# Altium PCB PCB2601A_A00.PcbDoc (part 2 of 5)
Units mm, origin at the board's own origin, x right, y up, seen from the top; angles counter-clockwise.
Board outline 30.4 x 51 mm, 8 copper layers (Top Layer, Signal Layer 2, Signal Layer 3, Signal Layer 4, Signal Layer 5, Signal Layer 6, Signal Layer 7, Bottom Layer), stack 1.492 mm thick; 194 components, 130 nets, 5039 pads, 478 vias.
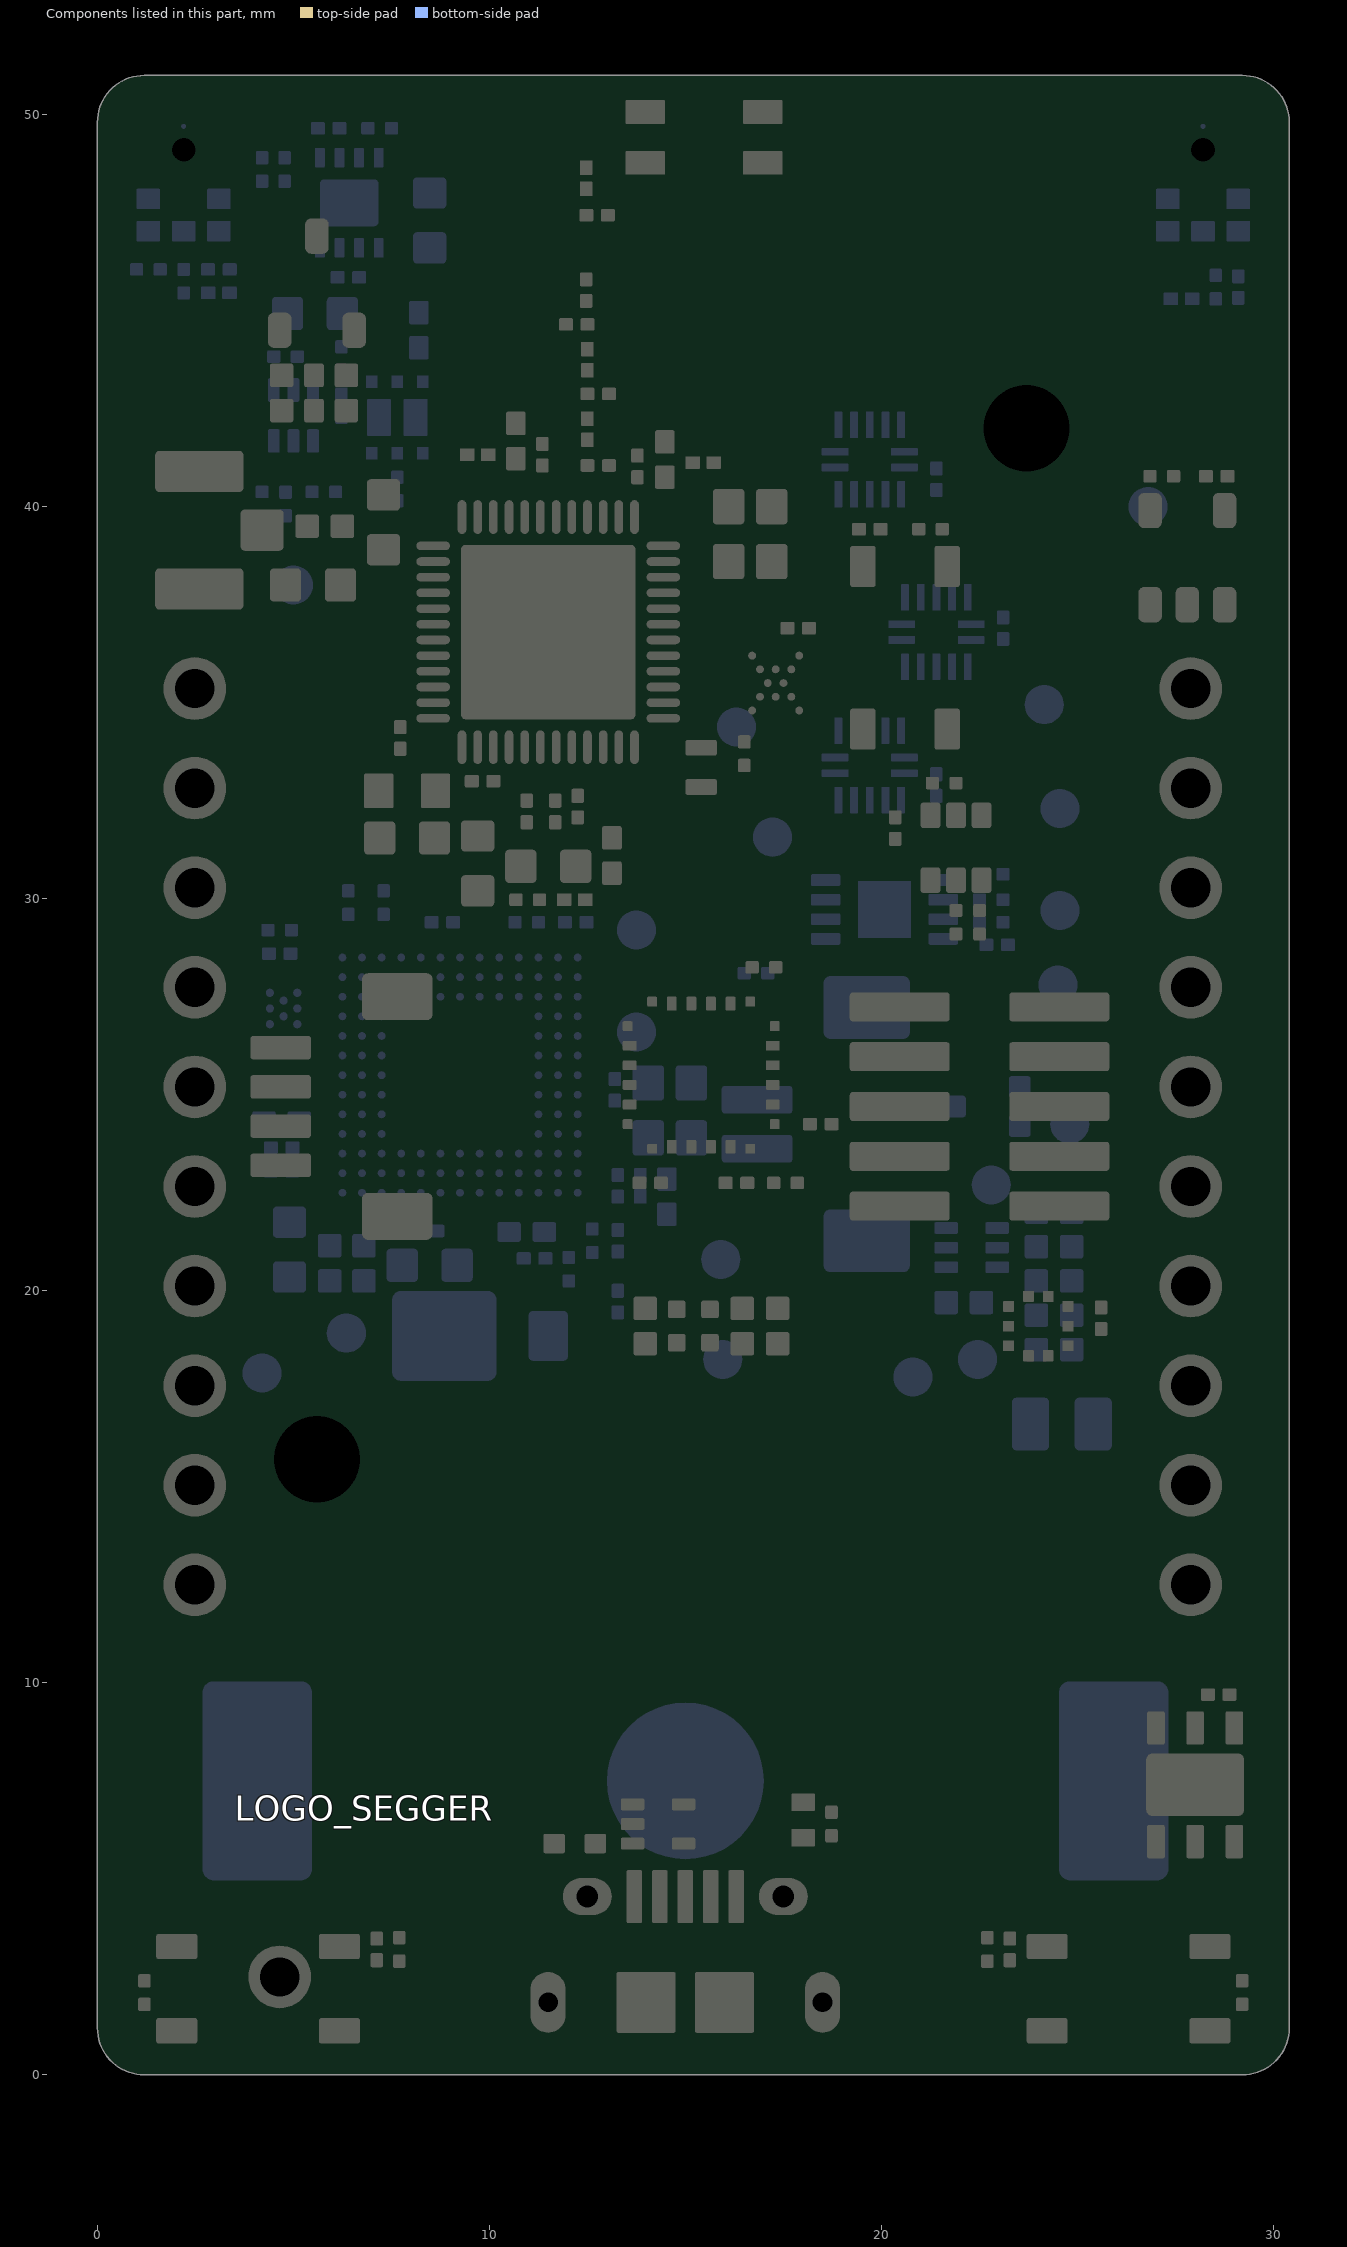
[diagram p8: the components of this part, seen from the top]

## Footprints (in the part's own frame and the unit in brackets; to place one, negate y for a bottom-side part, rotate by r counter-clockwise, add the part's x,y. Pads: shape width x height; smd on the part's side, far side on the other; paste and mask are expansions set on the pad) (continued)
LOGO_SEGGER_8.0X4.0_SM [mil] "(210607)" (continued)
  round 0.8 on Mech2: 1(-157.24,-66.18) 1(-157.24,-66.18) 1(-157.24,-65.7) 1(-157.24,-64.1) 1(-157.24,-62.5) 1(-157.24,-60.9) 1(-157.24,-59.22) 1(-157.24,-57.62) 1(-157.24,-56.02) 1(-157.24,-54.42) 1(-157.24,-52.82) 1(-157.24,-51.22) 1(-157.24,-49.62) 1(-157.24,-48.02) 1(-157.24,-46.42) 1(-157.24,-44.82) 1(-157.24,-43.14) 1(-157.24,-41.54) 1(-157.24,-39.94) 1(-157.24,-38.34) 1(-157.24,-36.74) 1(-157.24,-35.14) 1(-157.24,-33.54) 1(-157.24,-31.94) 1(-157.24,-30.34) 1(-157.24,-28.74) 1(-157.24,-27.06) 1(-157.24,-25.46) 1(-157.24,-23.86) 1(-157.24,-22.26) 1(-157.24,-20.66) 1(-157.24,-19.06) 1(-157.24,-17.46) 1(-157.24,-15.86) 1(-157.24,-14.26) 1(-157.24,-12.66) 1(-157.24,-10.98) 1(-157.24,-9.38) 1(-157.24,-7.78) 1(-157.24,-6.18) 1(-157.24,-4.58) 1(-157.24,-2.98) 1(-157.24,-1.38) 1(-157.24,0.22) 1(-157.24,1.82) 1(-157.24,3.42) 1(-157.24,5.1) 1(-157.24,6.7) 1(-157.24,8.3) 1(-157.24,9.9) 1(-157.24,11.5) 1(-157.24,13.1) 1(-157.24,14.7) 1(-157.24,16.3) 1(-157.24,17.9) 1(-157.24,19.5) 1(-157.24,21.18) 1(-157.24,22.78) 1(-157.24,24.38) 1(-157.24,25.98) 1(-157.24,27.58) 1(-157.24,29.18) 1(-157.24,30.78) 1(-157.24,32.38) 1(-157.24,33.98) 1(-157.24,35.58) 1(-157.24,37.26) 1(-157.24,38.86) 1(-157.24,40.46) 1(-157.24,42.06) 1(-157.24,43.66) 1(-157.24,45.26) 1(-157.24,46.86) 1(-157.24,48.46) 1(-157.24,50.06) 1(-157.24,51.66) 1(-157.24,53.34) 1(-157.24,54.94) 1(-157.24,56.54) 1(-157.24,58.14) 1(-157.24,59.74) 1(-157.24,61.34) 1(-157.24,62.94) 1(-157.24,64.54) 1(-157.24,66.14) 1(-157.24,66.38) 1(-157.24,66.38) 1(-157.08,-67.3) 1(-157.08,67.74) 1(-157,-68.1) 1(-157,-68.1) 1(-157,68.3) 1(-157,68.3) 1(-156.84,68.94) 1(-156.84,68.94) 1(-156.76,-68.9) 1(-156.68,-69.38) 1(-156.68,-69.38) 1(-156.68,69.42) 1(-156.68,69.5) 1(-156.68,69.5) 1(-156.52,-69.94) 1(-156.52,-69.94) 1(-156.52,70.14) 1(-156.52,70.14) 1(-156.28,-70.5) 1(-156.28,-70.5) 1(-156.2,-70.5) 1(-156.12,71.02) 1(-156.04,-71.14) 1(-156.04,-71.14) 1(-155.8,-71.7) 1(-155.8,-71.7) 1(-155.8,71.82) 1(-155.8,71.82) 1(-155.48,-72.26) 1(-155.48,-72.26) 1(-155.48,-72.1) 1(-155.32,72.62) 1(-155.16,72.94) 1(-155.16,72.94) 1(-154.84,-73.22) 1(-154.84,-73.22) 1(-154.84,73.42) 1(-154.84,73.42) 1(-154.44,-73.78) 1(-154.44,-73.78) 1(-154.44,-73.7) 1(-154.2,74.22) 1(-154.04,-74.18) 1(-154.04,-74.18) 1(-153.64,74.86) 1(-153.64,74.86) 1(-153.24,-75.14) 1(-153.24,-75.14) 1(-152.92,-75.3) 1(-152.76,75.74) 1(-152.76,75.74) 1(-152.68,75.82) 1(-152.28,76.06) 1(-152.28,76.06) 1(-151.8,-76.34) 1(-151.8,-76.34) 1(-151.32,-76.66) 1(-151.32,-76.66) 1(-151.32,76.86) 1(-151.32,76.86) 1(-150.76,-76.98) 1(-150.76,77.18) 1(-150.76,77.18) 1(-150.68,-66.18) 1(-150.68,-66.18) 1(-150.68,-65.7) 1(-150.68,-64.1) 1(-150.68,-62.5) 1(-150.68,-60.9) 1(-150.68,-59.22) 1(-150.68,-57.62) 1(-150.68,-56.02) 1(-150.68,-54.42) 1(-150.68,-52.82) 1(-150.68,-51.22) 1(-150.68,-49.62) 1(-150.68,-48.02) 1(-150.68,-46.42) 1(-150.68,-44.82) 1(-150.68,-43.14) 1(-150.68,-41.54) 1(-150.68,-39.94) 1(-150.68,-38.34) 1(-150.68,-36.74) 1(-150.68,-35.14) 1(-150.68,-33.54) 1(-150.68,-31.94) 1(-150.68,-30.34) 1(-150.68,-28.74) 1(-150.68,-27.06) 1(-150.68,-25.46) 1(-150.68,-23.86) 1(-150.68,-22.26) 1(-150.68,-20.66) 1(-150.68,-19.06) 1(-150.68,-17.46) 1(-150.68,-15.86) 1(-150.68,-14.26) 1(-150.68,-12.66) 1(-150.68,-10.98) 1(-150.68,-9.38) 1(-150.68,-7.78) 1(-150.68,-6.18) 1(-150.68,-4.58) 1(-150.68,-2.98) 1(-150.68,-1.38) 1(-150.68,0.22) 1(-150.68,1.82) 1(-150.68,3.42) 1(-150.68,5.1) 1(-150.68,6.7) 1(-150.68,8.3) 1(-150.68,9.9) 1(-150.68,11.5) 1(-150.68,13.1) 1(-150.68,14.7) 1(-150.68,16.3) 1(-150.68,17.9) 1(-150.68,19.5) 1(-150.68,21.18) 1(-150.68,22.78) 1(-150.68,24.38) 1(-150.68,25.98) 1(-150.68,27.58) 1(-150.68,29.18) 1(-150.68,30.78) 1(-150.68,32.38) 1(-150.68,33.98) 1(-150.68,35.58) 1(-150.68,37.26) 1(-150.68,38.86) 1(-150.68,40.46) 1(-150.68,42.06) 1(-150.68,43.66) 1(-150.68,45.26) 1(-150.68,46.86) 1(-150.68,48.46) 1(-150.68,50.06) 1(-150.68,51.66) 1(-150.68,53.34) 1(-150.68,54.94) 1(-150.68,56.54) 1(-150.68,58.14) 1(-150.68,59.74) 1(-150.68,61.34) 1(-150.68,62.94) 1(-150.68,64.54) 1(-150.68,66.14) 1(-150.68,66.38) 1(-150.68,66.38) 1(-150.6,-66.82) 1(-150.6,-66.82) 1(-150.6,-66.5) 1(-150.6,-66.5) 1(-150.6,66.7) 1(-150.6,66.7) 1(-150.6,67.02) 1(-150.6,67.02) 1(-150.44,-67.46) 1(-150.44,-67.46) 1(-150.44,-67.3) 1(-150.44,67.66) 1(-150.44,67.66) 1(-150.36,67.74) 1(-150.28,-67.78) 1(-150.28,-67.78) 1(-150.28,67.98) 1(-150.28,67.98) 1(-150.2,-77.3) 1(-150.2,-77.3) 1(-150.2,-68.1) 1(-150.2,-68.1) 1(-150.2,68.3) 1(-150.2,68.3) 1(-150.2,77.42) 1(-150.2,77.42) 1(-150.2,77.42) 1(-150.04,-68.42) 1(-150.04,-68.42) 1(-150.04,68.54) 1(-150.04,68.54) 1(-149.96,-68.66) 1(-149.96,-68.66) 1(-149.96,68.86) 1(-149.96,68.86) 1(-149.8,-68.98) 1(-149.8,-68.98) 1(-149.8,-68.9) 1(-149.8,69.1) 1(-149.8,69.1) 1(-149.72,-77.54) 1(-149.72,-77.54) 1(-149.72,77.74) 1(-149.72,77.74) 1(-149.64,69.42) 1(-149.64,69.42) 1(-149.64,69.42) 1(-149.48,-69.46) 1(-149.48,-69.46) 1(-149.48,69.66) 1(-149.48,69.66) 1(-149.24,-69.7) 1(-149.24,-69.7) 1(-149.24,69.9) 1(-149.24,69.9) 1(-149.08,-77.78) 1(-149.08,-77.78) 1(-149.08,-69.94) 1(-149.08,-69.94) 1(-149.08,70.14) 1(-149.08,70.14) 1(-149.08,77.98) 1(-149.08,77.98) 1(-148.84,-70.18) 1(-148.84,-70.18) 1(-148.68,-70.42) 1(-148.68,-70.42) 1(-148.52,-78.02) 1(-148.52,-78.02) 1(-148.52,78.14) 1(-148.52,78.14) 1(-148.44,-70.58) 1(-148.44,-70.58) 1(-148.44,-70.5) 1(-148.44,70.78) 1(-148.44,70.78) 1(-148.2,70.94) 1(-148.2,70.94) 1(-148.12,71.02) 1(-148.04,-70.98) 1(-148.04,-70.98) 1(-148.04,71.18) 1(-148.04,71.18) 1(-147.88,-78.18) 1(-147.88,-78.18) 1(-147.88,78.3) 1(-147.88,78.3) 1(-147.8,-71.14) 1(-147.8,-71.14) 1(-147.8,71.34) 1(-147.8,71.34) 1(-147.48,-71.3) 1(-147.48,-71.3) 1(-147.48,71.42) 1(-147.48,71.42) 1(-147.32,-78.34) 1(-147.32,-78.34) 1(-147.32,78.46) 1(-147.32,78.46) 1(-147.24,-71.38) 1(-147.24,-71.38) 1(-147,-71.54) 1(-147,-71.54) 1(-147,71.74) 1(-147,71.74) 1(-146.76,-71.62) 1(-146.76,-71.62) 1(-146.76,71.82) 1(-146.76,71.82) 1(-146.68,78.62) 1(-146.68,78.62) 1(-146.44,-71.78) 1(-146.44,-71.78) 1(-146.44,71.9) 1(-146.44,71.9) 1(-146.04,78.7) 1(-146.04,78.7) 1(-145.96,-71.94) 1(-145.96,-71.94) 1(-145.96,72.06) 1(-145.96,72.06) 1(-145.64,-71.94) 1(-145.64,-71.94) 1(-145.64,72.14) 1(-145.64,72.14) 1(-145.4,-78.58) 1(-145.4,-78.58) 1(-145.4,-72.02) 1(-145.4,-72.02) 1(-145.4,72.14) 1(-145.4,72.14) 1(-145.4,78.7) 1(-145.4,78.7) 1(-145.08,72.22) 1(-145.08,72.22) 1(-144.76,78.78) 1(-144.76,78.78) 1(-141.32,-53.06) 1(-141.32,-53.06) 1(-141.32,-52.58) 1(-141.32,-52.1) 1(-141.32,-52.1) 1(-141.32,52.3) 1(-141.32,52.3) 1(-141.32,53.26) 1(-141.32,53.26) 1(-141.24,-53.46) 1(-141.24,-53.46) 1(-141.24,-53.3) 1(-141.24,-53.3) 1(-141.24,-51.94) 1(-141.24,-51.94) 1(-141.24,52.06) 1(-141.24,52.06) 1(-141.24,53.5) 1(-141.24,53.5) 1(-141.24,53.5) 1(-141.24,53.66) 1(-141.24,53.66) 1(-141.16,-53.7) 1(-141.16,-53.7) 1(-141.16,-51.7) 1(-141.16,-51.7) 1(-141.16,51.9) 1(-141.16,51.9) 1(-141.16,51.9) 1(-141.16,53.9) 1(-141.16,53.9) 1(-141.08,-51.38) 1(-141.08,-51.38) 1(-141.08,51.5) 1(-141.08,51.5) 1(-141,-53.94) 1(-141,-53.94) 1(-141,54.06) 1(-141,54.06) 1(-140.92,-54.1) 1(-140.92,-54.1) 1(-140.92,54.3) 1(-140.92,54.3) 1(-140.84,-51.06) 1(-140.84,-51.06) 1(-140.84,-26.18) 1(-140.84,-26.18) 1(-140.84,-24.58) 1(-140.84,-22.9) 1(-140.84,-21.3) 1(-140.84,-19.7) 1(-140.84,-18.1) 1(-140.84,-16.5) 1(-140.84,-14.9) 1(-140.84,-13.3) 1(-140.84,-11.7) 1(-140.84,-10.1) 1(-140.84,-8.5) 1(-140.84,-6.82) 1(-140.84,-5.22) 1(-140.84,-3.62) 1(-140.84,-2.02) 1(-140.84,-0.42) 1(-140.84,1.18) 1(-140.84,2.78) 1(-140.84,4.38) 1(-140.84,5.98) 1(-140.84,7.58) 1(-140.84,9.26) 1(-140.84,10.86) 1(-140.84,12.46) 1(-140.84,14.06) 1(-140.84,15.66) 1(-140.84,17.26) 1(-140.84,18.86) 1(-140.84,20.46) 1(-140.84,22.06) 1(-140.84,23.66) 1(-140.84,25.34) 1(-140.84,26.3) 1(-140.84,26.3) 1(-140.84,51.18) 1(-140.84,51.18) 1(-140.76,-54.18) 1(-140.76,-50.98) 1(-140.68,-50.66) 1(-140.68,-50.66) 1(-140.68,50.86) 1(-140.68,50.86) 1(-140.6,-54.58) 1(-140.6,-54.58) 1(-140.6,54.78) 1(-140.6,54.78) 1(-140.44,-50.34) 1(-140.44,-50.34) 1(-140.44,50.46) 1(-140.44,50.46) 1(-140.36,54.94) 1(-140.36,54.94) 1(-140.28,50.3) 1(-140.2,-49.94) 1(-140.2,-49.94) 1(-140.2,50.14) 1(-140.2,50.14) 1(-140.2,55.1) 1(-140.04,25.34) 1(-139.88,-49.62) 1(-139.88,-49.62) 1(-139.88,49.82) 1(-139.88,49.82) 1(-139.88,55.42) 1(-139.88,55.42) 1(-139.72,-49.38) 1(-139.64,-55.54) 1(-139.64,-55.54) 1(-139.64,-24.58) 1(-139.64,55.74) 1(-139.64,55.74) 1(-139.16,-55.86) 1(-139,48.7) 1(-138.84,23.66) 1(-138.52,-47.78) 1(-138.36,-56.5) 1(-138.36,-56.5) 1(-138.36,-22.9) 1(-138.36,56.7) 1(-138.36,56.7) 1(-138.28,56.7) 1(-138.04,-56.66) 1(-138.04,-56.66) 1(-137.8,47.1) 1(-137.72,-56.9) 1(-137.72,-56.9) 1(-137.72,57.02) 1(-137.72,57.02) 1(-137.64,22.06) 1(-137.48,-56.98) 1(-137.48,-56.98) 1(-137.48,57.18) 1(-137.48,57.18) 1(-137.32,-46.18) 1(-137.16,-57.14) 1(-137.16,-57.14) 1(-137.16,-21.3) 1(-137.16,57.26) 1(-137.16,57.26) 1(-136.92,57.42) 1(-136.92,57.42) 1(-136.6,45.5) 1(-136.44,-57.38) 1(-136.44,-57.38) 1(-136.44,20.46) 1(-136.44,57.58) 1(-136.44,57.58) 1(-136.2,-57.38) 1(-136.2,-57.38) 1(-136.12,-44.58) 1(-135.96,-57.46) 1(-135.96,-57.46) 1(-135.96,-19.7) 1(-135.72,-57.46) 1(-135.72,-57.46) 1(-135.56,-57.38) 1(-135.56,-57.38) 1(-135.4,43.9) 1(-135.32,57.58) 1(-135.32,57.58) 1(-135.24,18.86) 1(-135.16,-57.38) 1(-135.16,-57.38) 1(-135,-57.3) 1(-135,-57.3) 1(-135,57.42) 1(-135,57.42) 1(-134.92,-42.98) 1(-134.76,-57.22) 1(-134.76,-57.22) 1(-134.76,-18.1) 1(-134.76,57.42) 1(-134.76,57.42) 1(-134.44,57.26) 1(-134.44,57.26) 1(-134.28,-56.98) 1(-134.28,-56.98) 1(-134.28,57.1) 1(-134.28,57.1) 1(-134.2,42.3) 1(-134.04,17.26) 1(-133.96,-56.66) 1(-133.96,-56.66) 1(-133.72,-41.38) 1(-133.72,56.7) 1(-133.64,-56.42) 1(-133.64,-56.42) 1(-133.64,56.62) 1(-133.64,56.62) 1(-133.56,-16.5) 1(-133.16,-55.86) 1(-133.16,-55.78) 1(-133.16,-55.78) 1(-133.16,55.98) 1(-133.16,55.98) 1(-133,40.62) 1(-132.84,-55.46) 1(-132.84,-55.46) 1(-132.84,15.66) 1(-132.84,55.58) 1(-132.84,55.58) 1(-132.6,-55.14) 1(-132.6,-55.14) 1(-132.6,55.26) 1(-132.6,55.26) 1(-132.52,-39.78) 1(-132.44,55.1) 1(-132.36,-14.9) 1(-131.88,-54.18) 1(-131.8,39.02) 1(-131.64,14.06) 1(-131.24,-38.1) 1(-131.24,53.5) 1(-131.16,-13.3) 1(-130.68,-52.58) 1(-130.6,37.42) 1(-130.36,12.46) 1(-130.04,-36.5) 1(-130.04,51.9) 1(-129.96,-11.7) 1(-129.48,-50.98) 1(-129.4,35.82) 1(-129.16,10.86) 1(-128.84,-34.9) 1(-128.84,50.3) 1(-128.76,-10.1) 1(-128.28,-49.38) 1(-128.12,34.22) 1(-127.96,9.26) 1(-127.64,-33.3) 1(-127.64,48.7) 1(-127.56,-8.5) 1(-127.08,-47.78) 1(-126.92,32.62) 1(-126.76,7.58) 1(-126.44,-31.7) 1(-126.44,47.1) 1(-126.36,-6.82) 1(-125.88,-46.18) 1(-125.72,31.02) 1(-125.56,5.98) 1(-125.24,-30.1) 1(-125.24,45.5) 1(-125.16,-5.22) 1(-124.68,-44.58) 1(-124.52,29.42) 1(-124.36,4.38) 1(-124.04,-28.5) 1(-123.96,-3.62) 1(-123.96,43.9) 1(-123.48,-42.98) 1(-123.32,27.82) 1(-123.16,2.78) 1(-122.84,-26.9) 1(-122.76,-2.02) 1(-122.76,42.3) 1(-122.28,-41.38) 1(-122.12,26.22) 1(-121.96,1.18) 1(-121.64,-25.3) 1(-121.56,40.62) 1(-121.48,-0.42) 1(-121.16,0.06) 1(-121.16,0.06) 1(-121.08,-39.78) 1(-120.92,24.54) 1(-120.44,-23.7) 1(-120.36,39.02) 1(-119.8,-38.1) 1(-119.72,22.94) 1(-119.24,-22.02) 1(-119.16,37.42) 1(-118.6,-36.5) 1(-118.52,21.34) 1(-118.04,-20.42) 1(-117.96,35.82) 1(-117.4,-34.9) 1(-117.32,19.74) 1(-116.84,-18.82) 1(-116.76,34.22) 1(-116.2,-33.3) 1(-116.12,18.14) 1(-115.64,-17.22) 1(-115.56,32.62) 1(-115,-31.7) 1(-114.92,16.54) 1(-114.44,-15.62) 1(-114.36,31.02) 1(-113.8,-30.1) 1(-113.72,14.94) 1(-113.24,-14.02) 1(-113.16,-53.06) 1(-113.16,-53.06) 1(-113.16,-52.58) 1(-113.16,-52.26) 1(-113.16,-52.26) 1(-113.16,29.42) 1(-113.16,52.38) 1(-113.16,52.38) 1(-113.16,53.18) 1(-113.16,53.18) 1(-113.08,-53.22) 1(-113.08,-53.22) 1(-113.08,-52.02) 1(-113.08,-52.02) 1(-113.08,-51.86) 1(-113.08,-51.86) 1(-113.08,52.06) 1(-113.08,52.06) 1(-113.08,52.22) 1(-113.08,52.22) 1(-113.08,53.42) 1(-113.08,53.42) 1(-113,-53.46) 1(-113,-53.46) 1(-113,-51.62) 1(-113,-51.62) 1(-113,51.82) 1(-113,51.82) 1(-113,51.98) 1(-113,53.58) 1(-113,53.58) 1(-113,53.58) 1(-112.92,-53.62) 1(-112.92,-53.62) 1(-112.84,-53.86) 1(-112.84,-53.86) 1(-112.84,51.5) 1(-112.84,51.5) 1(-112.84,54.06) 1(-112.84,54.06) 1(-112.68,-54.1) 1(-112.68,-54.1) 1(-112.68,-50.98) 1(-112.68,-50.98) 1(-112.68,-50.98) 1(-112.68,51.1) 1(-112.68,51.1) 1(-112.68,54.22) 1(-112.68,54.22) 1(-112.6,-54.34) 1(-112.6,-54.34) 1(-112.6,-54.18) 1(-112.6,-28.5) 1(-112.6,54.46) 1(-112.6,54.46) 1(-112.52,13.34) 1(-112.44,-50.58) 1(-112.44,-50.58) 1(-112.44,54.7) 1(-112.44,54.7) 1(-112.2,-54.74) 1(-112.2,-54.74) 1(-112.2,50.46) 1(-112.2,50.46) 1(-112.2,54.94) 1(-112.2,54.94) 1(-112.12,50.38) 1(-112.04,-54.98) 1(-112.04,-54.98) 1(-112.04,-12.42) 1(-112.04,55.18) 1(-112.04,55.18) 1(-112.04,55.18) 1(-111.96,50.06) 1(-111.96,50.06) 1(-111.88,27.82) 1(-111.8,-55.22) 1(-111.8,-55.22) 1(-111.8,55.42) 1(-111.8,55.42) 1(-111.72,-49.62) 1(-111.72,-49.62) 1(-111.72,49.74) 1(-111.72,49.74) 1(-111.56,-49.38) 1(-111.48,-55.46) 1(-111.48,-55.46) 1(-111.48,55.66) 1(-111.48,55.66) 1(-111.4,-26.9) 1(-111.32,11.74) 1(-111.24,-55.78) 1(-111.24,-55.78) 1(-111.24,55.9) 1(-111.24,55.9) 1(-111.08,-55.86) 1(-110.92,48.78) 1(-110.84,-56.02) 1(-110.84,-56.02) 1(-110.84,-10.82) 1(-110.84,56.22) 1(-110.84,56.22) 1(-110.68,26.22) 1(-110.52,56.38) 1(-110.52,56.38) 1(-110.28,-47.78) 1(-110.2,-56.5) 1(-110.2,-56.5) 1(-110.2,-25.3) 1(-110.12,10.14) 1(-109.96,56.86) 1(-109.88,-56.66) 1(-109.88,-56.66) 1(-109.88,56.86) 1(-109.88,56.86) 1(-109.72,47.18) 1(-109.64,-56.82) 1(-109.64,-56.82) 1(-109.64,-9.22) 1(-109.64,57.02) 1(-109.64,57.02) 1(-109.48,24.54) 1(-109.32,-56.98) 1(-109.32,-56.98) 1(-109.32,57.18) 1(-109.32,57.18) 1(-109.08,-57.14) 1(-109.08,-57.14) 1(-109.08,-46.18) 1(-109.08,57.26) 1(-109.08,57.26) 1(-109,-23.7) 1(-108.92,8.46) 1(-108.76,-57.22) 1(-108.76,-57.22) 1(-108.76,57.42) 1(-108.76,57.42) 1(-108.44,-7.62) 1(-108.44,45.58) 1(-108.28,-57.38) 1(-108.28,-57.38) 1(-108.28,22.94) 1(-108.28,57.58) 1(-108.28,57.58) 1(-108.04,-57.38) 1(-108.04,-57.38) 1(-107.8,-57.46) 1(-107.8,-57.46) 1(-107.8,-44.58) 1(-107.8,-22.02) 1(-107.72,6.86) 1(-107.4,-57.46) 1(-107.4,-57.46) 1(-107.24,-57.38) 1(-107.24,-57.38) 1(-107.24,-5.94) 1(-107.24,43.98) 1(-107.08,21.34) 1(-107,-57.38) 1(-107,-57.38) 1(-107,57.58) 1(-107,57.58) 1(-106.68,-57.22) 1(-106.68,-57.22) 1(-106.68,57.42) 1(-106.68,57.42) 1(-106.6,-42.98) 1(-106.6,-20.42) 1(-106.52,5.26) 1(-106.44,-57.14) 1(-106.44,-57.14) 1(-106.44,57.34) 1(-106.44,57.34) 1(-106.28,57.26) 1(-106.28,57.26) 1(-106.12,-56.98) 1(-106.12,-56.98) 1(-106.12,57.1) 1(-106.12,57.1) 1(-106.04,-4.34) 1(-105.96,42.38) 1(-105.88,19.74) 1(-105.8,-56.74) 1(-105.8,-56.74) 1(-105.8,56.86) 1(-105.8,56.86) 1(-105.72,56.86) 1(-105.56,-56.42) 1(-105.56,-56.42) 1(-105.4,-18.82) 1(-105.32,-41.38) 1(-105.32,3.66) 1(-105.24,-56.18) 1(-105.24,-56.18) 1(-105.24,56.3) 1(-105.24,56.3) 1(-105,-55.86) 1(-105,-55.86) 1(-105,-55.86) 1(-105,55.98) 1(-105,55.98) 1(-104.76,-2.74) 1(-104.76,40.78) 1(-104.68,-55.54) 1(-104.68,-55.54) 1(-104.68,18.14) 1(-104.68,55.66) 1(-104.68,55.66) 1(-104.44,-55.14) 1(-104.44,-55.14) 1(-104.44,55.34) 1(-104.44,55.34) 1(-104.28,55.18) 1(-104.12,-39.78) 1(-104.12,-17.22) 1(-104.12,2.06) 1(-103.72,-54.18) 1(-103.56,-1.14) 1(-103.48,16.54) 1(-103.48,39.1) 1(-103.08,53.58) 1(-102.92,-38.1) 1(-102.92,-15.62) 1(-102.92,0.46) 1(-102.6,0.14) 1(-102.6,0.14) 1(-102.52,-52.58) 1(-102.28,14.94) 1(-102.28,37.5) 1(-101.8,51.98) 1(-101.72,-14.02) 1(-101.64,-36.5) 1(-101.24,-50.98) 1(-101.08,13.34) 1(-101.08,35.9) 1(-100.6,50.38) 1(-100.52,-12.42) 1(-100.44,-34.9) 1(-100.04,-49.38) 1(-99.8,11.74) 1(-99.8,34.3) 1(-99.32,-10.82) 1(-99.32,48.78) 1(-99.16,-33.3) 1(-98.76,-47.78) 1(-98.6,10.14) 1(-98.6,32.7) 1(-98.12,-9.22) 1(-98.12,47.18) 1(-97.96,-31.7) 1(-97.56,-46.18) 1(-97.4,8.46) 1(-97.32,31.1) 1(-96.92,-7.62) 1(-96.84,45.58) 1(-96.68,-30.1) 1(-96.28,-44.58) 1(-96.2,6.86) 1(-96.12,29.5) 1(-95.72,-5.94) 1(-95.64,43.98) 1(-95.48,-28.5) 1(-95.08,-42.98) 1(-95,5.26) 1(-94.84,27.9) 1(-94.52,-4.34) 1(-94.36,42.38) 1(-94.2,-26.9) 1(-93.8,-41.38) 1(-93.8,3.66) 1(-93.64,26.3) 1(-93.48,-2.98) 1(-93.48,-2.98) 1(-93.48,3.26) 1(-93.48,3.26) 1(-93.32,-2.74) 1(-93.24,-2.66) 1(-93.24,-2.66) 1(-93.24,2.86) 1(-93.24,2.86) 1(-93.16,40.78) 1(-93,-25.3) 1(-93,-2.34) 1(-93,-2.34) 1(-93,2.46) 1(-93,2.46) 1(-92.76,-1.94) 1(-92.76,-1.94) 1(-92.68,2.06) 1(-92.6,-39.78) 1(-92.52,-1.62) 1(-92.52,-1.62) 1(-92.52,1.82) 1(-92.52,1.82) 1(-92.36,-1.3) 1(-92.36,-1.3) 1(-92.36,1.42) 1(-92.36,1.42) 1(-92.36,24.7) 1(-92.28,-1.14) 1(-92.12,-0.9) 1(-92.12,-0.9) 1(-92.12,1.1) 1(-92.12,1.1) 1(-91.96,-0.58) 1(-91.96,-0.58) 1(-91.96,-0.34) 1(-91.96,-0.34) 1(-91.96,0.54) 1(-91.96,0.54) 1(-91.96,0.7) 1(-91.96,0.7) 1(-91.96,39.1) 1(-91.88,-0.18) 1(-91.88,-0.18) 1(-91.88,-0.02) 1(-91.88,-0.02) 1(-91.88,0.14) 1(-91.88,0.14) 1(-91.88,0.38) 1(-91.88,0.38) 1(-91.88,0.46) 1(-91.8,0.14) 1(-91.8,0.14) 1(-91.72,-23.7) 1(-91.32,-38.1) 1(-91.16,23.02) 1(-90.68,37.5) 1(-90.52,-22.02) 1(-90.12,-36.5) 1(-89.88,21.42) 1(-89.48,35.9) 1(-89.24,-20.42) 1(-88.84,-34.9) 1(-88.68,19.82) 1(-88.2,34.3) 1(-88.04,-18.82) 1(-87.64,-33.3) 1(-87.4,18.22) 1(-87,32.7) 1(-86.84,-17.22) 1(-86.36,-31.7) 1(-86.2,16.62) 1(-85.72,31.1) 1(-85.56,-15.62) 1(-85.16,-30.1) 1(-85,15.02) 1(-84.52,29.5) 1(-84.36,-14.02) 1(-83.88,-28.5) 1(-83.72,13.42) 1(-83.24,27.9) 1(-83.08,-12.42) 1(-82.68,-26.9) 1(-82.52,11.82) 1(-82.04,26.3) 1(-81.88,-10.82) 1(-81.4,-25.3) 1(-81.24,10.22) 1(-80.76,24.7) 1(-80.6,-9.22) 1(-80.2,-23.7) 1(-80.04,8.62) 1(-79.72,-8.02) 1(-79.72,-8.02) 1(-79.72,8.22) 1(-79.72,8.22) 1(-79.56,23.02) 1(-79.4,-7.62) 1(-78.92,-22.02) 1(-78.92,-6.98) 1(-78.92,-6.98) 1(-78.92,7.1) 1(-78.92,7.1) 1(-78.76,6.94) 1(-78.68,-6.58) 1(-78.68,-6.58) 1(-78.68,6.78) 1(-78.68,6.78) 1(-78.36,-6.26) 1(-78.36,-6.26) 1(-78.36,6.46) 1(-78.36,6.46) 1(-78.36,21.42) 1(-78.12,-5.94) 1(-78.12,-5.94) 1(-78.12,-5.94) 1(-78.12,6.14) 1(-78.12,6.14) 1(-77.8,-5.7) 1(-77.8,-5.7) 1(-77.72,-20.42) 1(-77.56,-5.38) 1(-77.56,-5.38) 1(-77.56,5.58) 1(-77.56,5.58) 1(-77.48,-5.3) 1(-77.48,-5.3) 1(-77.48,5.58) 1(-77.48,5.58) 1(-77.4,5.5) 1(-77.4,5.5) 1(-77.08,19.82) 1(-77,-5.22) 1(-77,-5.22) 1(-77,5.42) 1(-77,5.42) 1(-76.52,-5.22) 1(-76.52,-5.22) 1(-76.52,5.34) 1(-76.52,5.34) 1(-76.44,-18.82) 1(-76.12,-5.14) 1(-76.12,-5.14) 1(-75.88,18.22) 1(-75.24,-17.22) 1(-74.6,16.62) 1(-73.96,-15.62) 1(-73.4,15.02) 1(-73,-14.34) 1(-73,-14.34) 1(-73,14.54) 1(-73,14.54) 1(-72.68,-36.26) 1(-72.68,-36.26) 1(-72.68,-35.86) 1(-72.68,-34.26) 1(-72.68,-34.26) 1(-72.68,-34.26) 1(-72.6,-50.58) 1(-72.6,-50.58) 1(-72.6,-36.66) 1(-72.6,-36.66) 1(-72.6,-33.78) 1(-72.6,-33.78) 1(-72.52,-51.22) 1(-72.52,-51.22) 1(-72.52,-50.9) 1(-72.52,-50.9) 1(-72.52,-50.34) 1(-72.52,-50.26) 1(-72.52,-50.26) 1(-72.52,-49.94) 1(-72.52,-49.94) 1(-72.52,-37.14) 1(-72.52,-37.14) 1(-72.44,-51.62) 1(-72.44,-51.62) 1(-72.44,-49.62) 1(-72.44,-49.62) 1(-72.44,-37.46) 1(-72.44,-33.3) 1(-72.44,-33.3) 1(-72.36,-49.38) 1(-72.36,-49.38) 1(-72.36,-37.94) 1(-72.36,-37.94) 1(-72.36,-32.82) 1(-72.36,-32.82) 1(-72.28,-51.94) 1(-72.28,-51.94) 1(-72.28,-32.66) 1(-72.2,-52.26) 1(-72.2,-52.26) 1(-72.2,-51.94) 1(-72.2,-49.06) 1(-72.2,-49.06) 1(-72.2,-32.34) 1(-72.2,-32.34) 1(-72.04,-52.58) 1(-72.04,-52.58) 1(-72.04,-48.82) 1(-72.04,-48.82) 1(-72.04,-38.74) 1(-72.04,-38.74) 1(-72.04,-31.94) 1(-72.04,-31.94) 1(-71.96,-48.74) 1(-71.8,-52.98) 1(-71.8,-52.98) 1(-71.8,-48.58) 1(-71.8,-48.58) 1(-71.8,-39.06) 1(-71.8,-31.46) 1(-71.8,-31.46) 1(-71.72,-39.38) 1(-71.72,-39.38) 1(-71.64,-53.3) 1(-71.64,-53.3) 1(-71.64,-48.34) 1(-71.64,-48.34) 1(-71.56,-39.78) 1(-71.56,-39.78) 1(-71.56,-31.06) 1(-71.56,-31.06) 1(-71.56,-31.06) 1(-71.32,-53.62) 1(-71.32,-53.62) 1(-71.32,-53.54) 1(-71.32,-40.1) 1(-71.32,-40.1) 1(-71.24,-30.66) 1(-71.24,-30.66) 1(-71.16,-48.02) 1(-71.16,-48.02) 1(-71.08,-53.94) 1(-71.08,-53.94) 1(-71,-30.26) 1(-71,-30.26) 1(-70.84,-47.86) 1(-70.84,-47.86) 1(-70.68,-40.74) 1(-70.6,-47.7) 1(-70.6,-47.7) 1(-70.2,-41.22) 1(-70.2,-41.22) 1(-70.2,-29.46) 1(-70.12,-54.9) 1(-70.12,-54.9) 1(-69.96,-47.54) 1(-69.96,-47.54) 1(-69.96,-29.22) 1(-69.96,-29.22) 1(-69.8,-55.14) 1(-69.8,-55.14) 1(-69.64,-55.14) 1(-69.56,-41.7) 1(-69.56,-41.7) 1(-69.56,-28.9) 1(-69.56,-28.9) 1(-69.4,-55.38) 1(-69.4,-55.38) 1(-69.16,-41.94) 1(-69.16,-41.94) 1(-69,-55.7) 1(-69,-55.7) 1(-68.68,-42.18) 1(-68.68,-42.18) 1(-68.6,-28.26) 1(-68.6,-28.26) 1(-68.52,-47.54) 1(-68.52,-47.54) 1(-68.44,-56.02) 1(-68.44,-56.02) 1(-68.36,-42.34) 1(-68.28,-42.42) 1(-68.28,-42.42) 1(-68.12,-28.02) 1(-68.12,-28.02) 1(-67.88,-27.86) 1(-67.8,-47.78) 1(-67.8,-47.78) 1(-67.72,-42.66) 1(-67.72,-42.66) 1(-67.64,-27.7) 1(-67.64,-27.7) 1(-67.56,-47.94) 1(-67.56,-47.94) 1(-67.32,-48.02) 1(-67.32,-48.02) 1(-67.16,-56.66) 1(-67.16,-56.66) 1(-67.16,-42.82) 1(-67.16,-42.82) 1(-67.08,-48.18) 1(-67.08,-48.18) 1(-67.08,-27.46) 1(-67.08,-27.46) 1(-66.76,-56.82) 1(-66.68,-48.58) 1(-66.68,-48.58) 1(-66.6,-56.9) 1(-66.6,-56.9) 1(-66.6,-43.06) 1(-66.6,-43.06) 1(-66.52,-27.3) 1(-66.52,-27.3) 1(-66.44,-48.74) 1(-66.44,-48.74) 1(-66.36,-48.74) 1(-66.04,-43.22) 1(-66.04,-43.22) 1(-65.96,-27.06) 1(-65.96,-27.06) 1(-65.8,-49.38) 1(-65.8,-49.38) 1(-65.56,-49.7) 1(-65.56,-49.7) 1(-65.48,-35.38) 1(-65.48,-35.38) 1(-65.48,-34.34) 1(-65.48,-34.34) 1(-65.4,-43.46) 1(-65.4,-43.46) 1(-65.4,-34.26) 1(-65.4,-34.1) 1(-65.4,-34.1) 1(-65.4,-26.9) 1(-65.4,-26.9) 1(-65.32,-35.86) 1(-65.32,-35.86) 1(-65.32,-35.7) 1(-65.32,-35.7) 1(-65.24,-50.02) 1(-65.24,-50.02) 1(-65.24,-35.86) 1(-65.24,-33.78) 1(-65.24,-33.78) 1(-65.24,-33.54) 1(-65.24,-33.54) 1(-65.08,-36.1) 1(-65.08,-36.1) 1(-65.08,-33.38) 1(-65.08,-33.38) 1(-65,-50.42) 1(-65,-50.42) 1(-65,-50.34) 1(-64.92,-36.34) 1(-64.92,-36.34) 1(-64.92,-33.06) 1(-64.92,-33.06) 1(-64.68,-57.62) 1(-64.68,-57.62) 1(-64.68,-43.7) 1(-64.68,-43.7) 1(-64.68,-36.58) 1(-64.68,-36.58) 1(-64.52,-50.9) 1(-64.52,-50.9) 1(-64.52,-32.66) 1(-64.44,-32.58) 1(-64.44,-32.58) 1(-64.36,-36.82) 1(-64.36,-36.82) 1(-64.28,-51.22) 1(-64.28,-51.22) 1(-64.28,-32.5) 1(-64.28,-32.5) 1(-64.12,-32.34) 1(-64.12,-32.34) 1(-64.12,-26.58) 1(-64.12,-26.58) 1(-63.88,-32.18) 1(-63.88,-32.18) 1(-63.64,-51.7) 1(-63.64,-51.7) 1(-63.56,-43.94) 1(-63.56,-37.3) 1(-63.56,-37.3) 1(-63.48,-32.02) 1(-63.48,-32.02) 1(-63.48,-26.5) 1(-63.48,-26.5) 1(-63.4,-57.94) 1(-63.4,-57.94) 1(-63.32,-51.86) 1(-63.32,-51.86) 1(-63.24,-44.02) 1(-63.24,-44.02) 1(-63.16,-51.94) 1(-63.08,-37.54) 1(-63.08,-37.54) 1(-63.08,-37.46) 1(-63,-52.1) 1(-63,-52.1) 1(-63,-31.78) 1(-63,-31.78) 1(-62.76,-58.02) 1(-62.76,-58.02) 1(-62.76,-26.42) 1(-62.76,-26.42) 1(-62.68,-52.26) 1(-62.68,-52.26) 1(-62.6,-37.7) 1(-62.6,-37.7) 1(-62.52,-31.62) 1(-62.52,-31.62) 1(-62.44,-44.18) 1(-62.44,-44.18) 1(-62.04,-58.18) 1(-62.04,-58.18) 1(-62.04,-37.94) 1(-62.04,-37.94) 1(-62.04,-26.26) 1(-62.04,-26.26) 1(-62.04,-26.26) 1(-61.96,-31.46) 1(-61.96,-31.46) 1(-61.88,-52.58) 1(-61.88,-52.58) 1(-61.64,-44.42) 1(-61.64,-44.42) 1(-61.48,-52.66) 1(-61.48,-52.66) 1(-61.4,-31.38) 1(-61.4,-31.38) 1(-61.32,-26.26) 1(-61.32,-26.26) 1(-61.24,-58.26) 1(-61.24,-58.26) 1(-61.08,-52.82) 1(-61.08,-52.82) 1(-60.76,-44.58) 1(-60.76,-44.58) 1(-60.6,-26.18) 1(-60.6,-26.18) 1(-60.52,-58.34) 1(-60.52,-58.34) 1(-60.52,-44.58) 1(-60.52,-44.58) 1(-60.2,-44.66) 1(-60.2,-44.66) 1(-60.12,-52.98) 1(-60.12,-52.98) 1(-60.12,-38.42) 1(-60.12,-38.42) 1(-60.12,-31.22) 1(-60.12,-31.22) 1(-59.72,-58.34) 1(-59.72,-58.34) 1(-59.72,-53.06) 1(-59.72,-53.06) 1(-59.32,-38.58) 1(-59.32,-38.58) 1(-59.16,-53.06) 1(-59.16,-53.06) 1(-58.92,-31.22) 1(-58.92,-31.22) 1(-58.84,-58.42) 1(-58.84,-58.42) 1(-58.68,-53.14) 1(-58.68,-53.14) 1(-58.6,-38.74) 1(-58.6,-38.74) 1(-58.44,-31.3) 1(-58.44,-31.3) 1(-58.12,-53.14) 1(-58.12,-53.14) 1(-58.12,-45.14) 1(-58.12,-45.14) 1(-58.04,-38.9) 1(-58.04,-38.9) 1(-58.04,-31.3) 1(-58.04,-31.3) 1(-57.56,-31.38) 1(-57.56,-31.38) 1(-57.56,-26.18) 1(-57.56,-26.18) 1(-57.48,-38.98) 1(-57.48,-38.98) 1(-57.32,-53.06) 1(-57.32,-53.06) 1(-57.24,-58.42) 1(-57.24,-58.42) 1(-57.16,-45.38) 1(-57.16,-45.38) 1(-57.16,-31.38) 1(-57.16,-31.38) 1(-57,-39.06) 1(-57,-39.06) 1(-56.84,-26.26) 1(-56.84,-26.26) 1(-56.76,-39.06) 1(-56.76,-31.54) 1(-56.76,-31.54) 1(-56.52,-53.06) 1(-56.52,-53.06) 1(-56.52,-45.54) 1(-56.44,-58.34) 1(-56.44,-58.34) 1(-56.2,-26.26) 1(-56.2,-26.26) 1(-56.2,-26.26) 1(-56.12,-39.3) 1(-56.12,-39.3) 1(-55.96,-31.7) 1(-55.96,-31.7) 1(-55.64,-58.34) 1(-55.64,-58.34) 1(-55.64,-31.86) 1(-55.64,-31.86) 1(-55.48,-26.34) 1(-55.48,-26.34) 1(-55.4,-45.86) 1(-55.4,-45.86) 1(-55.24,-39.46) 1(-55.24,-39.46) 1(-55.24,-32.02) 1(-55.24,-32.02) 1(-55.08,-52.9) 1(-55.08,-52.9) 1(-54.92,-58.18) 1(-54.92,-58.18) 1(-54.84,-26.42) 1(-54.84,-26.42) 1(-54.68,-46.1) 1(-54.68,-46.1) 1(-54.6,-32.34) 1(-54.6,-32.34) 1(-54.44,-52.74) 1(-54.44,-52.74) 1(-54.36,-32.5) 1(-54.36,-32.5) 1(-54.2,-58.18) 1(-54.2,-58.18) 1(-54.2,-26.58) 1(-54.2,-26.58) 1(-54.04,-46.42) 1(-54.04,-46.42) 1(-54.04,-32.74) 1(-54.04,-32.74) 1(-54.04,-32.66) 1(-53.88,-52.58) 1(-53.88,-52.58) 1(-53.8,-32.9) 1(-53.8,-32.9) 1(-53.64,-52.5) 1(-53.64,-52.5) 1(-53.64,-39.78) 1(-53.64,-39.78) 1(-53.64,-26.74) 1(-53.64,-26.74) 1(-53.4,-52.34) 1(-53.4,-52.34) 1(-53.4,-46.66) 1(-53.4,-46.66) 1(-53.24,-33.46) 1(-53.24,-33.46) 1(-53.16,-52.26) 1(-53.16,-52.26) 1(-53.08,-33.7) 1(-53.08,-33.7) 1(-53,-26.9) 1(-53,-26.9) 1(-52.92,-52.1) 1(-52.92,-52.1) 1(-52.92,-46.98) 1(-52.92,-46.98) 1(-52.76,-57.86) 1(-52.76,-57.86) 1(-52.68,-52.02) 1(-52.68,-52.02) 1(-52.6,-51.94) 1(-52.52,-51.86) 1(-52.52,-51.86) 1(-52.52,-47.14) 1(-52.44,-47.22) 1(-52.44,-47.22) 1(-52.44,-34.26) 1(-52.36,-40.1) 1(-52.36,-40.1) 1(-52.36,-34.42) 1(-52.36,-34.42) 1(-52.28,-51.7) 1(-52.28,-51.7) 1(-52.2,-47.38) 1(-52.2,-47.38) 1(-52.12,-34.58) 1(-52.12,-34.58) 1(-51.96,-34.82) 1(-51.96,-34.82) 1(-51.88,-27.22) 1(-51.88,-27.22) 1(-51.8,-51.22) 1(-51.8,-51.22) 1(-51.8,-40.26) 1(-51.8,-40.26) 1(-51.72,-51.06) 1(-51.72,-51.06) 1(-51.56,-50.9) 1(-51.56,-50.9) 1(-51.56,-48.02) 1(-51.56,-48.02) 1(-51.48,-57.54) 1(-51.48,-57.54) 1(-51.48,-50.66) 1(-51.48,-50.66) 1(-51.4,-50.5) 1(-51.4,-50.5) 1(-51.32,-50.34) 1(-51.32,-50.26) 1(-51.32,-50.26) 1(-51.32,-40.34) 1(-51.32,-40.34) 1(-51.24,-50.1) 1(-51.24,-50.1) 1(-51.24,-49.86) 1(-51.24,-49.86) 1(-51.16,-49.62) 1(-51.16,-49.62) 1(-51.16,-48.82) 1(-51.16,-48.82) 1(-51.16,-48.74) 1(-51,-35.46) 1(-51,-35.46) 1(-50.92,-57.38) 1(-50.92,-57.38) 1(-50.76,-35.54) 1(-50.76,-35.54) 1(-50.76,-27.7) 1(-50.76,-27.7) 1(-50.52,-40.66) 1(-50.52,-40.66) 1(-50.52,-35.7) 1(-50.52,-35.7) 1(-50.36,-27.86) 1(-50.28,-57.14) 1(-50.28,-57.14) 1(-50.28,-40.74) 1(-50.28,-35.7) 1(-50.28,-35.7) 1(-50.28,-27.94) 1(-50.28,-27.94) 1(-49.8,-35.86) 1(-49.8,-35.86) 1(-49.72,-40.9) 1(-49.72,-40.9) 1(-49.72,-28.18) 1(-49.72,-28.18) 1(-49.56,-35.86) 1(-49.56,-35.86) 1(-49.48,-56.82) 1(-49.4,-35.86) 1(-49.32,-35.94) 1(-49.32,-35.94) 1(-49.24,-28.5) 1(-49.24,-28.5) 1(-49.16,-56.66) 1(-49.16,-56.66) 1(-48.92,-41.22) 1(-48.92,-41.22) 1(-48.84,-28.66) 1(-48.84,-28.66) 1(-48.68,-56.34) 1(-48.68,-56.34) 1(-48.68,-35.94) 1(-48.68,-35.94) 1(-48.52,-35.86) 1(-48.52,-28.98) 1(-48.52,-28.98) 1(-48.36,-35.86) 1(-48.36,-35.86) 1(-48.28,-41.54) 1(-48.28,-41.54) 1(-48.12,-56.02) 1(-48.12,-56.02) 1(-48.04,-35.86) 1(-48.04,-35.86) 1(-47.88,-29.46) 1(-47.88,-29.46) 1(-47.8,-29.46) 1(-47.72,-41.78) 1(-47.72,-41.78) 1(-47.72,-35.7) 1(-47.72,-35.7) 1(-47.64,-55.78) 1(-47.64,-55.78) 1(-47.48,-35.62) 1(-47.48,-35.62) 1(-47.24,-55.38) 1(-47.24,-55.38) 1(-47.16,-35.46) 1(-47.16,-35.46) 1(-47,-30.34) 1(-47,-30.34) 1(-46.92,-55.14) 1(-46.92,-35.38) 1(-46.92,-35.38) 1(-46.84,-42.34) 1(-46.76,-55.06) 1(-46.76,-55.06) 1(-46.76,-42.42) 1(-46.76,-42.42) 1(-46.76,-30.74) 1(-46.76,-30.74) 1(-46.68,-35.14) 1(-46.68,-35.14) 1(-46.52,-30.98) 1(-46.52,-30.98) 1(-46.44,-34.98) 1(-46.44,-34.98) 1(-46.44,-31.06) 1(-46.36,-42.74) 1(-46.36,-42.74) 1(-46.36,-31.38) 1(-46.36,-31.38) 1(-46.2,-31.62) 1(-46.2,-31.62) 1(-46.04,-31.94) 1(-46.04,-31.94) 1(-45.96,-43.14) 1(-45.96,-43.14) 1(-45.96,-34.26) 1(-45.96,-34.26) 1(-45.96,-34.26) 1(-45.96,-32.26) 1(-45.96,-32.26) 1(-45.8,-33.78) 1(-45.8,-33.78) 1(-45.8,-32.66) 1(-45.8,-32.58) 1(-45.8,-32.58) 1(-45.64,-53.94) 1(-45.64,-53.94) 1(-45.56,-43.46) 1(-45.56,-43.46) 1(-45.4,-53.54) 1(-45.32,-53.46) 1(-45.32,-53.46) 1(-45.24,-43.86) 1(-45.24,-43.86) 1(-45.16,-43.94) 1(-45.08,-53.06) 1(-45.08,-53.06) 1(-44.92,-44.34) 1(-44.92,-44.34) 1(-44.84,-52.58) 1(-44.84,-52.58) 1(-44.68,-44.74) 1(-44.68,-44.74) 1(-44.6,-52.18) 1(-44.6,-52.18) 1(-44.44,-51.94) 1(-44.44,-45.22) 1(-44.44,-45.22) 1(-44.36,-51.7) 1(-44.36,-51.7) 1(-44.28,-45.7) 1(-44.28,-45.7) 1(-44.28,-45.54) 1(-44.2,-51.22) 1(-44.2,-51.22) 1(-44.12,-50.66) 1(-44.12,-50.66) 1(-44.12,-46.26) 1(-44.12,-46.26) 1(-44.04,-46.74) 1(-44.04,-46.74) 1(-43.96,-50.34) 1(-43.96,-50.18) 1(-43.96,-50.18) 1(-43.96,-49.62) 1(-43.96,-49.62) 1(-43.96,-47.3) 1(-43.96,-47.3) 1(-43.96,-47.14) 1(-43.88,-49.06) 1(-43.88,-49.06) 1(-43.88,-48.74) 1(-43.88,-47.94) 1(-43.88,-47.94) 1(-38.12,-52.74) 1(-38.12,-52.74) 1(-38.12,-52.66) 1(-38.12,-51.06) 1(-38.12,-49.46) 1(-38.12,-47.86) 1(-38.12,-46.26) 1(-38.12,-44.66) 1(-38.12,-43.06) 1(-38.12,-41.46) 1(-38.12,-39.86) 1(-38.12,-38.18) 1(-38.12,-36.58) 1(-38.12,-34.98) 1(-38.12,-33.38) 1(-38.12,-31.78) 1(-38.12,-31.78) 1(-38.12,-31.78) 1(-38.04,-54.02) 1(-38.04,-54.02) 1(-38.04,-53.38) 1(-38.04,-53.38) 1(-38.04,-31.06) 1(-38.04,-31.06) 1(-38.04,-30.5) 1(-38.04,-30.5) 1(-37.96,-54.58) 1(-37.96,-54.58) 1(-37.96,-54.26) 1(-37.96,-30.18) 1(-37.96,-29.94) 1(-37.96,-29.94) 1(-37.8,-55.3) 1(-37.8,-55.3) 1(-37.8,-55.06) 1(-37.8,-55.06) 1(-37.8,-29.38) 1(-37.8,-29.38) 1(-37.8,-29.14) 1(-37.8,-29.14) 1(-37.72,-28.98) 1(-37.72,-28.98) 1(-37.64,-55.78) 1(-37.64,-55.78) 1(-37.64,-28.74) 1(-37.64,-28.74) 1(-37.56,-55.94) 1(-37.56,-55.94) 1(-37.56,-55.94) 1(-37.56,-28.58) 1(-37.56,-28.58) 1(-37.56,-28.58) 1(-37.4,-56.1) 1(-37.4,-56.1) 1(-37.4,-28.42) 1(-37.4,-28.42) 1(-37.24,-56.42) 1(-37.24,-56.42) 1(-37.24,-28.1) 1(-37.24,-28.1) 1(-37,-56.66) 1(-37,-56.66) 1(-36.84,-56.74) 1(-36.84,-56.74) 1(-36.84,-27.7) 1(-36.84,-27.7) 1(-36.68,-56.9) 1(-36.68,-56.9) 1(-36.68,-27.62) 1(-36.68,-27.62) 1(-36.52,-27.46) 1(-36.52,-27.46) 1(-36.36,-57.06) 1(-36.36,-57.06) 1(-36.36,-27.46) 1(-36.36,-27.46) 1(-36.12,-57.14) 1(-36.12,-57.14) 1(-36.12,-27.3) 1(-36.12,-27.3) 1(-35.96,-57.22) 1(-35.96,-57.22) 1(-35.96,-27.22) 1(-35.96,-27.22) 1(-35.72,-57.3) 1(-35.72,-57.3) 1(-35.72,-27.22) 1(-35.72,-27.22) 1(-35.24,-27.06) 1(-35.24,-27.06) 1(-34.76,-57.46) 1(-34.76,-57.46) 1(-34.76,-26.98) 1(-34.76,-26.98) 1(-34.76,-26.98) 1(-34.2,-57.54) 1(-34.2,-57.54) 1(-34.2,-26.98) 1(-34.2,-26.98) 1(-33.56,-26.9) 1(-33.56,-26.9) 1(-30.76,-51.94) 1(-30.76,-51.94) 1(-30.76,-51.06) 1(-30.76,-49.46) 1(-30.76,-47.86) 1(-30.76,-46.26) 1(-30.76,-44.66) 1(-30.76,-44.02) 1(-30.76,-44.02) 1(-30.76,-38.74) 1(-30.76,-38.74) 1(-30.76,-38.18) 1(-30.76,-36.58) 1(-30.76,-34.98) 1(-30.76,-33.38) 1(-30.76,-32.26) 1(-30.76,-32.26) 1(-17,-38.74) 1(-17,-38.74) 1(-16.52,-44.02) 1(-16.52,-44.02) 1(-16.52,-38.82) 1(-16.52,-38.82) 1(-16.12,-43.94) 1(-16.12,-43.94) 1(-16.04,-38.82) 1(-16.04,-38.82) 1(-15.72,-43.94) 1(-15.72,-43.94) 1(-15.64,-38.9) 1(-15.64,-38.9) 1(-15.48,-26.9) 1(-15.48,-26.9) 1(-15.24,-38.9) 1(-15.24,-38.9) 1(-15,-32.26) 1(-15,-32.26) 1(-15,-26.98) 1(-15,-26.98) 1(-14.92,-43.78) 1(-14.92,-43.78) 1(-14.92,-39.06) 1(-14.92,-39.06) 1(-14.68,-43.62) 1(-14.68,-43.62) 1(-14.6,-39.14) 1(-14.6,-39.14) 1(-14.52,-32.18) 1(-14.52,-32.18) 1(-14.52,-26.98) 1(-14.52,-26.98) 1(-14.44,-26.98) 1(-14.36,-43.54) 1(-14.36,-43.54) 1(-14.28,-39.3) 1(-14.28,-39.3) 1(-14.12,-32.18) 1(-14.12,-32.18) 1(-14.04,-51.94) 1(-14.04,-51.94) 1(-14.04,-43.38) 1(-14.04,-43.38) 1(-13.8,-43.22) 1(-13.8,-43.22) 1(-13.8,-39.62) 1(-13.8,-39.62) 1(-13.72,-32.1) 1(-13.72,-32.1) 1(-13.72,-27.14) 1(-13.72,-27.14) 1(-13.64,-43.06) 1(-13.64,-42.98) 1(-13.64,-42.98) 1(-13.56,-57.54) 1(-13.56,-57.54) 1(-13.56,-52.02) 1(-13.56,-52.02) 1(-13.56,-39.86) 1(-13.4,-42.74) 1(-13.4,-42.74) 1(-13.4,-40.02) 1(-13.4,-40.02) 1(-13.4,-32.02) 1(-13.4,-32.02) 1(-13.4,-27.22) 1(-13.4,-27.22) 1(-13.32,-40.26) 1(-13.32,-40.26) 1(-13.16,-52.02) 1(-13.16,-52.02) 1(-13.16,-42.26) 1(-13.16,-42.26) 1(-13.16,-40.5) 1(-13.16,-40.5) 1(-13.08,-42.02) 1(-13.08,-42.02) 1(-13.08,-41.7) 1(-13.08,-41.7) 1(-13.08,-41.14) 1(-13.08,-41.14) 1(-13.08,-40.82) 1(-13.08,-40.82) 1(-13,-41.46) 1(-13,-41.38) 1(-13,-41.38) 1(-13,-31.86) 1(-13,-31.86) 1(-13,-27.3) 1(-13,-27.3) 1(-12.84,-31.78) 1(-12.76,-57.38) 1(-12.76,-57.38) 1(-12.76,-31.78) 1(-12.76,-31.78) 1(-12.76,-27.46) 1(-12.76,-27.46) 1(-12.44,-57.3) 1(-12.44,-57.3) 1(-12.44,-31.62) 1(-12.44,-31.62) 1(-12.44,-27.62) 1(-12.44,-27.62) 1(-12.36,-52.18) 1(-12.36,-52.18) 1(-12.2,-27.78) 1(-12.2,-27.78) 1(-12.04,-31.22) 1(-12.04,-31.22) 1(-11.8,-56.98) 1(-11.8,-56.98) 1(-11.72,-52.5) 1(-11.72,-52.5) 1(-11.64,-28.58) 1(-11.56,-56.82) 1(-11.56,-56.82) 1(-11.56,-30.5) 1(-11.56,-30.5) 1(-11.56,-28.74) 1(-11.56,-28.74) 1(-11.48,-30.26) 1(-11.48,-30.26) 1(-11.48,-30.18) 1(-11.48,-28.98) 1(-11.48,-28.98) 1(-11.4,-52.66) 1(-11.24,-56.66) 1(-11.24,-56.66) 1(-11.24,-52.82) 1(-11.24,-52.82) 1(-10.92,-53.3) 1(-10.92,-53.3) 1(-10.76,-55.94) 1(-10.76,-53.46) 1(-10.76,-53.46) 1(-10.6,-55.7) 1(-10.6,-55.7) 1(-10.6,-53.78) 1(-10.6,-53.78) 1(-10.52,-55.38) 1(-10.52,-55.38) 1(-10.52,-54.26) 1(-10.52,-54.1) 1(-10.52,-54.1) 1(-6.92,-42.34) 1(-6.92,-42.26) 1(-6.92,-42.26) 1(-6.84,-44.02) 1(-6.84,-44.02) 1(-6.84,-43.94) 1(-6.84,-43.14) 1(-6.84,-43.14) 1(-6.84,-41.3) 1(-6.84,-41.3) 1(-6.84,-40.74) 1(-6.84,-40.42) 1(-6.84,-40.42) 1(-6.76,-44.9) 1(-6.76,-44.9) 1(-6.76,-39.54) 1(-6.76,-39.54) 1(-6.68,-39.06) 1(-6.6,-45.54) 1(-6.44,-46.5) 1(-6.44,-46.5) 1(-6.44,-37.94) 1(-6.44,-37.94) 1(-6.28,-37.46) 1(-6.2,-47.3) 1(-6.2,-47.3) 1(-6.2,-47.14) 1(-6.2,-37.14) 1(-6.2,-37.14) 1(-6.04,-48.02) 1(-6.04,-48.02) 1(-6.04,-36.34) 1(-6.04,-36.34) 1(-5.8,-35.86) 1(-5.72,-48.82) 1(-5.72,-48.82) 1(-5.72,-48.74) 1(-5.4,-49.54) 1(-5.4,-49.54) 1(-5.08,-50.18) 1(-5.08,-50.18) 1(-5.08,-34.26) 1(-5.08,-34.18) 1(-5.08,-34.18) 1(-4.92,-50.34) 1(-4.68,-50.9) 1(-4.68,-50.9) 1(-4.28,-51.54) 1(-4.28,-51.54) 1(-4.28,-32.9) 1(-4.28,-32.9) 1(-4.12,-32.66) 1(-3.88,-51.94) 1(-3.32,-52.82) 1(-3.32,-52.82) 1(-3.32,-31.62) 1(-3.32,-31.62) 1(-2.76,-31.06) 1(-2.52,-53.54) 1(-1.64,-54.5) 1(-1.64,-54.5) 1(-1.64,-29.94) 1(-1.64,-29.94) 1(-1,-29.46) 1(-1,-29.46) 1(-1,-29.46) 1(-0.68,-55.14) 1(-0.36,-55.46) 1(-0.36,-55.46) 1(-0.36,-29.06) 1(-0.36,-29.06) 1(0.36,-55.94) 1(0.36,-55.94) 1(0.36,-28.58) 1(0.36,-28.58) 1(0.84,-43.38) 1(0.84,-43.38) 1(0.84,-42.34) 1(0.84,-40.98) 1(0.84,-40.98) 1(0.92,-43.94) 1(0.92,-40.74) 1(1,-56.26) 1(1,-56.26) 1(1,-28.18) 1(1,-28.18) 1(1.08,-45.06) 1(1.08,-45.06) 1(1.16,-39.06) 1(1.16,-38.74) 1(1.16,-38.74) 1(1.24,-45.62) 1(1.24,-45.62) 1(1.24,-45.54) 1(1.4,-46.1) 1(1.4,-46.1) 1(1.48,-46.66) 1(1.48,-46.66) 1(1.56,-37.46) 1(1.64,-37.3) 1(1.64,-37.3) 1(1.72,-56.66) 1(1.72,-56.66) 1(1.72,-47.14) 1(1.72,-47.14) 1(1.72,-47.14) 1(1.72,-27.86) 1(1.88,-47.54) 1(1.88,-47.54) 1(1.88,-36.82) 1(1.88,-36.82) 1(2.04,-36.34) 1(2.04,-36.34) 1(2.12,-56.82) 1(2.12,-48.02) 1(2.12,-48.02) 1(2.28,-35.94) 1(2.28,-35.94) 1(2.36,-35.86) 1(2.44,-27.54) 1(2.44,-27.54) 1(2.6,-48.82) 1(2.6,-48.82) 1(2.6,-48.74) 1(2.6,-35.54) 1(2.6,-35.54) 1(2.84,-35.14) 1(2.84,-35.14) 1(3.16,-57.3) 1(3.16,-57.3) 1(3.16,-34.74) 1(3.16,-34.74) 1(3.24,-27.22) 1(3.24,-27.22) 1(3.4,-34.42) 1(3.4,-34.42) 1(3.56,-50.02) 1(3.56,-50.02) 1(3.56,-34.26) 1(3.96,-50.34) 1(4.12,-33.7) 1(4.12,-33.7) 1(4.2,-50.66) 1(4.2,-50.66) 1(4.52,-33.38) 1(4.52,-33.38) 1(4.6,-50.98) 1(4.6,-50.98) 1(4.76,-57.78) 1(4.76,-57.78) 1(4.84,-33.14) 1(4.84,-33.14) 1(4.84,-26.74) 1(4.84,-26.74) 1(5.4,-51.46) 1(5.4,-51.46) 1(5.64,-57.94) 1(5.64,-57.94) 1(5.64,-32.66) 1(5.64,-32.66) 1(5.64,-32.66) 1(5.64,-26.58) 1(5.64,-26.58) 1(5.88,-51.7) 1(5.88,-51.7) 1(6.12,-32.42) 1(6.12,-32.42) 1(6.28,-51.94) 1(6.28,-51.94) 1(6.44,-58.1) 1(6.44,-58.1) 1(6.44,-51.94) 1(6.52,-32.26) 1(6.52,-32.26) 1(6.52,-26.42) 1(6.52,-26.42) 1(7.32,-58.26) 1(7.32,-58.26) 1(7.48,-31.94) 1(7.48,-31.94) 1(7.48,-26.26) 1(7.48,-26.26) 1(7.48,-26.26) 1(7.96,-31.86) 1(7.96,-31.86) 1(8.2,-58.34) 1(8.2,-58.34) 1(8.2,-52.58) 1(8.2,-52.58) 1(8.36,-26.26) 1(8.36,-26.26) 1(8.44,-31.7) 1(8.44,-31.7) 1(8.76,-52.66) 1(8.76,-52.66) 1(8.92,-31.62) 1(8.92,-31.62) 1(9.16,-58.42) 1(9.16,-58.42) 1(9.24,-52.74) 1(9.24,-52.74) 1(9.32,-26.18) 1(9.32,-26.18) 1(9.48,-31.62) 1(9.48,-31.62) 1(9.8,-52.82) 1(9.8,-52.82) 1(10.04,-31.54) 1(10.04,-31.54) 1(10.92,-58.42) 1(10.92,-58.42) 1(11.08,-43.78) 1(11.08,-43.78) 1(11.08,-43.22) 1(11.08,-43.22) 1(11.08,-31.54) 1(11.08,-31.54) 1(11.16,-44.1) 1(11.16,-44.1) 1(11.16,-43.94) 1(11.16,-42.98) 1(11.16,-42.98) 1(11.24,-42.66) 1(11.24,-42.66) 1(11.32,-42.42) 1(11.32,-42.42) 1(11.4,-44.82) 1(11.4,-44.82) 1(11.4,-42.34) 1(11.4,-42.26) 1(11.4,-42.26) 1(11.56,-42.02) 1(11.56,-42.02) 1(11.64,-31.62) 1(11.64,-31.62) 1(11.72,-45.3) 1(11.72,-45.3) 1(11.72,-41.86) 1(11.72,-41.86) 1(11.8,-52.82) 1(11.8,-52.82) 1(11.88,-41.62) 1(11.88,-41.62) 1(12.12,-45.54) 1(12.12,-41.46) 1(12.12,-41.46) 1(12.12,-31.62) 1(12.12,-31.62) 1(12.12,-26.18) 1(12.12,-26.18) 1(12.2,-52.74) 1(12.2,-52.74) 1(12.36,-41.38) 1(12.36,-41.38) 1(12.52,-58.26) 1(12.52,-58.26) 1(12.6,-52.74) 1(12.6,-52.74) 1(12.68,-45.94) 1(12.68,-45.94) 1(12.68,-41.22) 1(12.68,-41.22) 1(12.68,-26.26) 1(12.68,-26.26) 1(12.68,-26.26) 1(12.92,-46.02) 1(12.92,-46.02) 1(12.92,-41.14) 1(12.92,-41.14) 1(13.08,-31.78) 1(13.08,-31.78) 1(13.24,-58.1) 1(13.24,-58.1) 1(13.32,-26.34) 1(13.32,-26.34) 1(13.48,-31.94) 1(13.48,-31.94) 1(13.56,-46.18) 1(13.56,-46.18) 1(13.56,-40.98) 1(13.56,-40.98) 1(13.88,-32.02) 1(13.88,-32.02) 1(13.88,-26.42) 1(13.88,-26.42) 1(14.04,-58.02) 1(14.04,-58.02) 1(14.2,-52.42) 1(14.2,-52.42) 1(14.28,-32.18) 1(14.28,-32.18) 1(14.44,-26.42) 1(14.44,-26.42) 1(14.52,-52.26) 1(14.52,-52.26) 1(14.68,-57.78) 1(14.68,-57.78) 1(14.68,-32.42) 1(14.68,-32.42) 1(14.92,-52.1) 1(14.92,-52.1) 1(15,-26.58) 1(15,-26.58) 1(15.08,-32.58) 1(15.08,-32.58) 1(15.24,-52.02) 1(15.24,-52.02) 1(15.32,-51.94) 1(15.32,-32.66) 1(15.4,-57.62) 1(15.4,-57.62) 1(15.48,-32.82) 1(15.48,-32.82) 1(15.56,-51.86) 1(15.56,-51.86) 1(15.56,-26.66) 1(15.56,-26.66) 1(15.88,-51.62) 1(15.88,-51.62) 1(15.88,-33.14) 1(15.88,-33.14) 1(16.04,-57.3) 1(16.04,-57.3) 1(16.12,-26.82) 1(16.12,-26.82) 1(16.2,-33.38) 1(16.2,-33.38) 1(16.52,-51.3) 1(16.52,-51.3) 1(16.6,-33.78) 1(16.6,-33.78) 1(16.68,-57.06) 1(16.68,-57.06) 1(16.68,-26.9) 1(16.68,-26.9) 1(17,-34.1) 1(17,-34.1) 1(17.16,-50.82) 1(17.16,-50.82) 1(17.16,-34.26) 1(17.16,-27.06) 1(17.16,-27.06) 1(17.24,-56.82) 1(17.32,-56.74) 1(17.32,-56.74) 1(17.32,-34.5) 1(17.32,-34.5) 1(17.64,-50.34) 1(17.72,-27.22) 1(17.72,-27.22) 1(17.88,-56.34) 1(17.88,-56.34) 1(17.88,-50.1) 1(17.88,-50.1) 1(17.96,-35.06) 1(17.96,-35.06) 1(18.12,-49.78) 1(18.12,-49.78) 1(18.2,-27.38) 1(18.2,-27.38) 1(18.52,-55.94) 1(18.52,-55.94) 1(18.52,-35.54) 1(18.52,-35.54) 1(18.6,-49.3) 1(18.6,-49.3) 1(18.68,-27.62) 1(18.68,-27.62) 1(18.76,-35.78) 1(18.76,-35.78) 1(18.92,-48.74) 1(19,-35.86) 1(19.16,-27.78) 1(19.16,-27.78) 1(19.24,-36.1) 1(19.24,-36.1) 1(19.4,-55.14) 1(19.4,-47.7) 1(19.4,-47.7) 1(19.4,-27.86) 1(19.48,-47.3) 1(19.48,-47.3) 1(19.56,-47.14) 1(19.64,-54.98) 1(19.64,-54.98) 1(19.64,-46.98) 1(19.64,-46.98) 1(19.72,-36.26) 1(19.72,-36.26) 1(19.8,-46.18) 1(19.8,-46.18) 1(19.88,-36.34) 1(19.88,-36.34) 1(20.2,-36.42) 1(20.2,-36.42) 1(20.44,-36.5) 1(20.44,-36.5) 1(20.44,-28.42) 1(20.44,-28.42) 1(20.68,-53.94) 1(20.68,-53.94) 1(20.68,-36.5) 1(20.68,-36.5) 1(20.92,-36.58) 1(20.92,-36.58) 1(21,-55.14) 1(21.24,-56.26) 1(21.24,-56.26) 1(21.4,-56.74) 1(21.4,-56.74) 1(21.48,-56.9) 1(21.48,-56.9) 1(21.48,-56.82) 1(21.56,-57.14) 1(21.56,-57.14) 1(21.56,-29.06) 1(21.56,-29.06) 1(22.2,-36.58) 1(22.2,-36.58) 1(22.2,-29.46) 1(22.36,-57.94) 1(22.36,-57.94) 1(22.52,-58.02) 1(22.52,-58.02) 1(22.52,-36.5) 1(22.52,-36.5) 1(22.52,-29.7) 1(22.52,-29.7) 1(22.76,-58.1) 1(22.76,-58.1) 1(22.76,-36.42) 1(22.76,-36.42) 1(22.92,-58.18) 1(22.92,-58.18) 1(23.08,-36.26) 1(23.08,-36.26) 1(23.16,-58.26) 1(23.16,-58.26) 1(23.32,-40.98) 1(23.32,-40.98) 1(23.4,-58.26) 1(23.4,-58.26) 1(23.56,-35.94) 1(23.56,-35.94) 1(23.64,-35.86) 1(23.64,-30.82) 1(23.64,-30.82) 1(23.72,-58.34) 1(23.72,-58.34) 1(23.88,-31.06) 1(23.96,-58.34) 1(23.96,-58.34) 1(23.96,-31.22) 1(23.96,-31.22) 1(24.28,-58.26) 1(24.28,-58.26) 1(24.28,-41.14) 1(24.28,-41.14) 1(24.28,-35.22) 1(24.28,-35.22) 1(24.44,-34.98) 1(24.44,-34.98) 1(24.44,-32.02) 1(24.44,-32.02) 1(24.52,-58.26) 1(24.52,-58.26) 1(24.52,-34.74) 1(24.52,-34.74) 1(24.52,-32.34) 1(24.52,-32.34) 1(24.68,-41.22) 1(24.68,-41.22) 1(24.68,-34.42) 1(24.68,-34.42) 1(24.68,-32.74) 1(24.68,-32.74) 1(24.68,-32.66) 1(24.76,-34.26) 1(24.76,-34.18) 1(24.76,-34.18) 1(24.76,-33.14) 1(24.76,-33.14) 1(24.84,-58.18) 1(24.84,-58.18) 1(25,-41.38) 1(25,-41.38) 1(25.08,-58.18) 1(25.08,-58.18) 1(25.32,-58.02) 1(25.32,-58.02) 1(25.32,-41.46) 1(25.32,-41.46) 1(25.56,-57.94) 1(25.56,-57.94) 1(25.8,-41.78) 1(25.8,-41.78) 1(26.2,-57.3) 1(26.2,-57.3) 1(26.2,-42.34) 1(26.28,-57.06) 1(26.28,-57.06) 1(26.28,-42.5) 1(26.28,-42.5) 1(26.36,-56.82) 1(26.36,-56.74) 1(26.36,-56.74) 1(26.44,-56.5) 1(26.44,-56.5) 1(26.52,-56.18) 1(26.52,-56.18) 1(26.52,-55.14) 1(26.52,-53.54) 1(26.52,-51.94) 1(26.52,-50.34) 1(26.52,-48.74) 1(26.52,-47.14) 1(26.52,-45.54) 1(26.52,-43.94) 1(26.52,-43.46) 1(26.52,-43.46) 1(32.12,-43.14) 1(32.12,-43.14) 1(32.12,-42.34) 1(32.12,-41.3) 1(32.12,-41.3) 1(32.2,-43.94) 1(32.2,-40.74) 1(32.28,-44.9) 1(32.28,-44.9) 1(32.28,-39.54) 1(32.28,-39.54) 1(32.36,-45.7) 1(32.36,-45.7) 1(32.36,-45.54) 1(32.36,-39.06) 1(32.36,-38.74) 1(32.36,-38.74) 1(32.52,-46.5) 1(32.52,-46.5) 1(32.52,-37.94) 1(32.52,-37.94) 1(32.68,-37.46) 1(32.76,-47.3) 1(32.76,-47.3) 1(32.76,-47.14) 1(33,-48.02) 1(33,-48.02) 1(33,-36.34) 1(33,-36.34) 1(33.16,-35.86) 1(33.24,-48.82) 1(33.24,-48.82) 1(33.24,-48.74) 1(33.24,-35.62) 1(33.24,-35.62) 1(33.56,-49.54) 1(33.56,-49.54) 1(33.56,-34.9) 1(33.56,-34.9) 1(33.96,-50.18) 1(33.96,-50.18) 1(33.96,-34.26) 1(33.96,-34.18) 1(33.96,-34.18) 1(34.04,-50.34) 1(34.28,-50.9) 1(34.28,-50.9) 1(34.28,-33.54) 1(34.28,-33.54) 1(34.76,-51.54) 1(34.76,-51.54) 1(34.76,-32.9) 1(34.76,-32.9) 1(34.92,-32.66) 1(35.08,-51.94) 1(35.16,-52.18) 1(35.16,-52.18) 1(35.16,-32.26) 1(35.16,-32.26) 1(35.64,-52.82) 1(35.64,-52.82) 1(35.64,-31.62) 1(35.64,-31.62) 1(36.2,-31.06) 1(36.44,-53.54) 1(36.76,-53.94) 1(36.76,-53.94) 1(36.76,-30.5) 1(36.76,-30.5) 1(37.4,-54.5) 1(37.4,-54.5) 1(37.4,-29.94) 1(37.4,-29.94) 1(37.96,-54.98) 1(37.96,-54.98) 1(37.96,-29.46) 1(37.96,-29.46) 1(37.96,-29.46) 1(38.36,-55.14) 1(38.6,-29.06) 1(38.6,-29.06) 1(38.68,-55.46) 1(38.68,-55.46) 1(39.32,-55.94) 1(39.32,-55.94) 1(39.32,-28.58) 1(39.32,-28.58) 1(39.8,-42.82) 1(39.8,-42.82) 1(39.8,-42.34) 1(39.8,-41.62) 1(39.8,-41.62) 1(39.88,-43.94) 1(39.88,-43.94) 1(39.88,-43.94) 1(39.88,-43.38) 1(39.88,-43.38) 1(39.88,-40.98) 1(39.88,-40.98) 1(39.88,-40.74) 1(39.88,-40.42) 1(39.88,-40.42) 1(39.96,-56.26) 1(39.96,-56.26) 1(39.96,-44.5) 1(39.96,-44.5) 1(39.96,-39.86) 1(39.96,-39.86) 1(39.96,-28.18) 1(39.96,-28.18) 1(40.12,-45.06) 1(40.12,-45.06) 1(40.12,-39.3) 1(40.12,-39.3) 1(40.2,-45.62) 1(40.2,-45.62) 1(40.2,-45.54) 1(40.2,-39.06) 1(40.2,-38.74) 1(40.2,-38.74) 1(40.28,-38.26) 1(40.28,-38.26) 1(40.36,-46.1) 1(40.36,-46.1) 1(40.52,-46.66) 1(40.52,-46.66) 1(40.52,-37.78) 1(40.52,-37.78) 1(40.6,-37.46) 1(40.68,-56.66) 1(40.68,-56.66) 1(40.68,-47.14) 1(40.68,-47.14) 1(40.76,-47.14) 1(40.76,-27.86) 1(40.76,-27.86) 1(40.76,-27.86) 1(40.84,-36.82) 1(40.84,-36.82) 1(40.92,-47.54) 1(40.92,-47.54) 1(41.08,-56.82) 1(41.08,-48.02) 1(41.08,-48.02) 1(41.08,-36.34) 1(41.08,-36.34) 1(41.32,-48.42) 1(41.32,-48.42) 1(41.4,-56.98) 1(41.4,-56.98) 1(41.4,-35.86) 1(41.64,-48.82) 1(41.64,-48.82) 1(41.64,-48.74) 1(41.8,-35.14) 1(41.8,-35.14) 1(41.88,-49.22) 1(41.88,-49.22) 1(42.12,-34.74) 1(42.12,-34.74) 1(42.2,-57.3) 1(42.2,-57.3) 1(42.2,-27.22) 1(42.2,-27.22) 1(42.44,-34.42) 1(42.44,-34.42) 1(42.52,-50.02) 1(42.52,-50.02) 1(42.6,-34.26) 1(42.76,-34.02) 1(42.76,-34.02) 1(42.84,-50.34) 1(42.84,-50.34) 1(42.92,-50.34) 1(43.08,-33.7) 1(43.08,-33.7) 1(43.48,-33.38) 1(43.48,-33.38) 1(43.64,-50.98) 1(43.64,-50.98) 1(43.8,-57.78) 1(43.8,-57.78) 1(43.8,-26.74) 1(43.8,-26.74) 1(43.96,-51.22) 1(43.96,-51.22) 1(44.44,-51.46) 1(44.44,-51.46) 1(44.68,-32.66) 1(45.08,-32.42) 1(45.08,-32.42) 1(45.24,-51.94) 1(45.24,-51.94) 1(45.4,-58.1) 1(45.4,-58.1) 1(45.4,-51.94) 1(45.48,-32.26) 1(45.48,-32.26) 1(46.28,-58.26) 1(46.28,-58.26) 1(46.44,-31.94) 1(46.44,-31.94) 1(46.44,-26.26) 1(46.44,-26.26) 1(46.44,-26.26) 1(46.92,-31.86) 1(46.92,-31.86) 1(47.16,-52.58) 1(47.16,-52.58) 1(47.24,-58.34) 1(47.24,-58.34) 1(47.32,-26.26) 1(47.32,-26.26) 1(47.4,-31.7) 1(47.4,-31.7) 1(47.72,-52.66) 1(47.72,-52.66) 1(47.96,-31.62) 1(47.96,-31.62) 1(48.12,-58.42) 1(48.12,-58.42) 1(48.2,-52.74) 1(48.2,-52.74) 1(48.28,-26.18) 1(48.28,-26.18) 1(48.44,-31.62) 1(48.44,-31.62) 1(48.76,-52.82) 1(48.76,-52.82) 1(49,-31.54) 1(49,-31.54) 1(49.88,-58.42) 1(49.88,-58.42) 1(50.04,-43.78) 1(50.04,-43.78) 1(50.04,-43.22) 1(50.04,-43.22) 1(50.12,-44.1) 1(50.12,-44.1) 1(50.12,-43.94) 1(50.12,-42.98) 1(50.12,-42.98) 1(50.12,-31.54) 1(50.12,-31.54) 1(50.2,-42.66) 1(50.2,-42.66) 1(50.28,-42.42) 1(50.28,-42.42) 1(50.36,-44.82) 1(50.36,-44.82) 1(50.36,-42.34) 1(50.36,-42.26) 1(50.36,-42.26) 1(50.52,-45.06) 1(50.52,-45.06) 1(50.52,-42.02) 1(50.52,-42.02) 1(50.6,-31.62) 1(50.6,-31.62) 1(50.76,-58.34) 1(50.76,-58.34) 1(50.76,-52.82) 1(50.76,-52.82) 1(50.92,-45.46) 1(50.92,-45.46) 1(50.92,-41.62) 1(50.92,-41.62) 1(51.08,-45.54) 1(51.08,-31.62) 1(51.08,-31.62) 1(51.08,-26.18) 1(51.08,-26.18) 1(51.16,-52.74) 1(51.16,-52.74) 1(51.16,-41.46) 1(51.16,-41.46) 1(51.4,-41.38) 1(51.4,-41.38) 1(51.48,-58.26) 1(51.48,-58.26) 1(51.56,-52.74) 1(51.56,-52.74) 1(51.64,-45.94) 1(51.64,-45.94) 1(51.64,-41.22) 1(51.64,-41.22) 1(51.72,-26.26) 1(51.72,-26.26) 1(51.72,-26.26) 1(51.88,-41.14) 1(51.88,-41.14) 1(51.96,-46.02) 1(51.96,-46.02) 1(52.04,-52.66) 1(52.04,-52.66) 1(52.04,-31.78) 1(52.04,-31.78) 1(52.2,-46.1) 1(52.2,-46.1) 1(52.28,-58.1) 1(52.28,-58.1) 1(52.44,-52.58) 1(52.44,-52.58) 1(52.44,-31.94) 1(52.44,-31.94) 1(52.52,-46.18) 1(52.52,-46.18) 1(52.52,-40.98) 1(52.52,-40.98) 1(52.76,-52.5) 1(52.76,-52.5) 1(52.84,-26.42) 1(52.84,-26.42) 1(52.92,-32.02) 1(52.92,-32.02) 1(53,-58.02) 1(53,-58.02) 1(53.16,-52.42) 1(53.16,-52.42) 1(53.32,-32.18) 1(53.32,-32.18) 1(53.4,-26.42) 1(53.4,-26.42) 1(53.48,-52.26) 1(53.48,-52.26) 1(53.72,-57.78) 1(53.72,-57.78) 1(53.72,-32.42) 1(53.72,-32.42) 1(53.88,-52.1) 1(53.88,-52.1) 1(54.04,-32.58) 1(54.04,-32.58) 1(54.04,-26.58) 1(54.04,-26.58) 1(54.2,-52.02) 1(54.2,-52.02) 1(54.28,-51.94) 1(54.28,-32.66) 1(54.36,-57.62) 1(54.36,-57.62) 1(54.44,-32.82) 1(54.44,-32.82) 1(54.6,-51.86) 1(54.6,-51.86) 1(54.6,-26.66) 1(54.6,-26.66) 1(54.84,-51.62) 1(54.84,-51.62) 1(54.84,-33.14) 1(54.84,-33.14) 1(55.08,-57.3) 1(55.08,-57.3) 1(55.08,-26.82) 1(55.08,-26.82) 1(55.24,-51.46) 1(55.24,-51.46) 1(55.24,-33.38) 1(55.24,-33.38) 1(55.48,-51.3) 1(55.48,-51.3) 1(55.56,-33.78) 1(55.56,-33.78) 1(55.64,-26.9) 1(55.64,-26.9) 1(55.72,-57.06) 1(55.72,-57.06) 1(55.96,-34.1) 1(55.96,-34.1) 1(56.12,-50.82) 1(56.12,-50.82) 1(56.12,-27.06) 1(56.12,-27.06) 1(56.2,-56.82) 1(56.2,-34.26) 1(56.28,-56.74) 1(56.28,-56.74) 1(56.36,-50.58) 1(56.36,-50.58) 1(56.68,-50.34) 1(56.68,-50.34) 1(56.68,-50.34) 1(56.68,-27.22) 1(56.68,-27.22) 1(56.92,-56.34) 1(56.92,-56.34) 1(56.92,-50.1) 1(56.92,-50.1) 1(56.92,-35.06) 1(56.92,-35.06) 1(57.16,-49.78) 1(57.16,-49.78) 1(57.16,-27.38) 1(57.16,-27.38) 1(57.32,-49.54) 1(57.32,-49.54) 1(57.48,-55.94) 1(57.48,-55.94) 1(57.48,-35.54) 1(57.48,-35.54) 1(57.56,-49.3) 1(57.56,-49.3) 1(57.64,-27.62) 1(57.64,-27.62) 1(57.72,-48.98) 1(57.72,-48.98) 1(57.72,-35.78) 1(57.72,-35.78) 1(57.88,-48.74) 1(57.96,-48.66) 1(57.96,-48.66) 1(57.96,-35.86) 1(58.12,-48.34) 1(58.12,-48.34) 1(58.12,-27.78) 1(58.12,-27.78) 1(58.2,-48.02) 1(58.2,-48.02) 1(58.2,-36.1) 1(58.2,-36.1) 1(58.36,-55.14) 1(58.36,-47.7) 1(58.36,-47.7) 1(58.36,-27.86) 1(58.52,-47.3) 1(58.52,-47.3) 1(58.6,-47.14) 1(58.6,-46.98) 1(58.6,-46.98) 1(58.76,-46.18) 1(58.76,-46.18) 1(59.16,-54.5) 1(59.16,-54.5) 1(59.4,-36.5) 1(59.4,-36.5) 1(59.4,-28.42) 1(59.4,-28.42) 1(59.64,-53.94) 1(59.64,-53.94) 1(59.64,-36.5) 1(59.64,-36.5) 1(59.96,-55.14) 1(59.96,-36.58) 1(59.96,-36.58)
